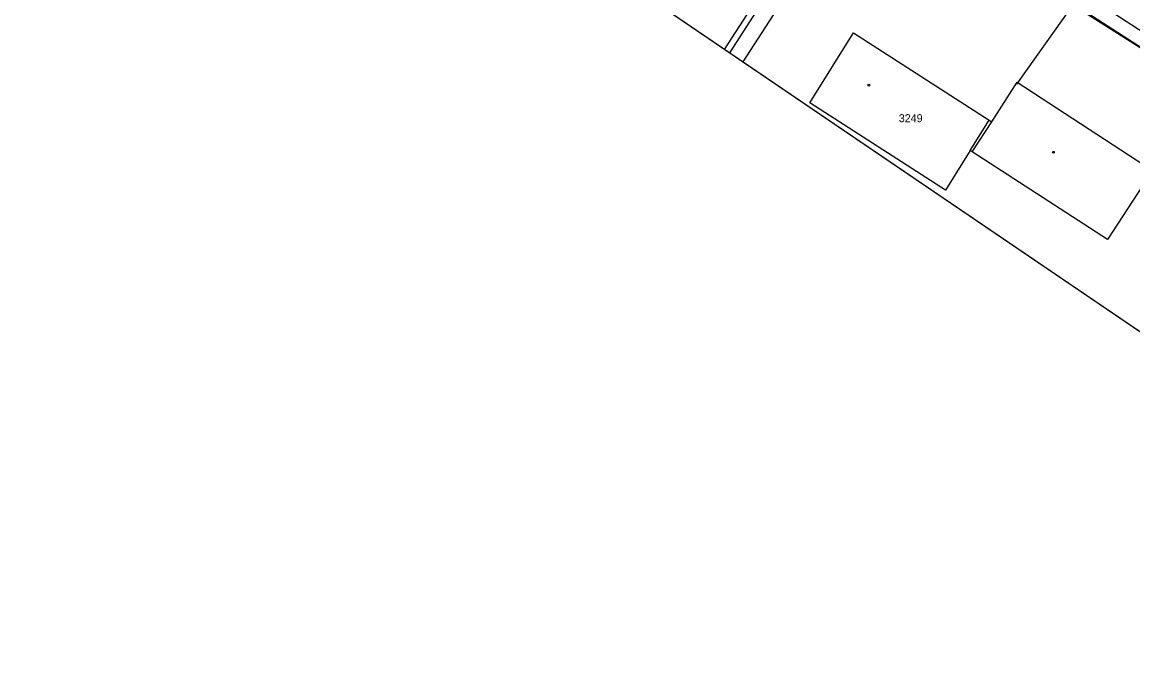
# Model space of a CAD drawing. Extents: x -621145 to -620023, y -1122866 to -1121971.
# Drawn here: x -620936.6 to -620728.5, y -1122562.6 to -1122442.6 of the extents above; entities that cross this region are included whole.
import ezdxf

# ---------------------------------------------------------------- set-up
doc = ezdxf.new("R2010")
doc.units = 0
for name, color, linetype in [('GasNet', 7, 'Continuous'), ('itself', 7, 'Continuous'), ('RÁMY', 7, 'Continuous'), ('VAS vodovod', 7, 'Continuous'), ('Vrstva 55', 7, 'Continuous'), ('Vrstva 56', 7, 'Continuous'), ('Vrstva 57', 7, 'Continuous')]:
    doc.layers.add(name, color=color, linetype=linetype)

msp = doc.modelspace()

# ---------------------------------------------------------------- linework, layer by layer
at = {"layer": 'GasNet'}
msp.add_lwpolyline([(-620780.25, -1122411.07), (-620780.49, -1122411.62), (-620780.55, -1122411.72), (-620781.12, -1122412.67), (-620781.53, -1122413.35), (-620786.71, -1122421.95), (-620795.26, -1122434.7), (-620804.04, -1122448.32)], dxfattribs=at)
at = {"layer": 'itself'}
msp.add_lwpolyline([(-620721.67, -1122450.84), (-620745.77, -1122435.49), (-620776.46, -1122415.3), (-620776.4, -1122414.33), (-620775.69, -1122413.16), (-620774.76, -1122411.29), (-620776.99, -1122409.87), (-620778.95, -1122408.64), (-620781.22, -1122407.1), (-620786.31, -1122404.21), (-620793, -1122399.61), (-620794.81, -1122398.03), (-620806.31, -1122390.88), (-620816.81, -1122384.12), (-620818.8, -1122383.36), (-620822.25, -1122382.5), (-620843.1, -1122368.97), (-620871.29, -1122351.22), (-620896.98, -1122334.7), (-620917.62, -1122321.73), (-620932.53, -1122311.53), (-620939.77, -1122306.09)], dxfattribs=at)
at = {"layer": 'RÁMY'}
for points in [[(-621061.56, -1122093.92), (-620106.07, -1122742.82), (-620189.51, -1122865.67), (-621144.99, -1122216.77)], [(-620887.83, -1122211.9), (-620106.07, -1122742.82), (-620189.51, -1122865.67), (-620971.26, -1122334.75)]]:
    msp.add_lwpolyline(points, close=True, dxfattribs=at)
at = {"layer": 'VAS vodovod'}
for points in [[(-620783.05, -1122410.36), (-620779.49, -1122412.44), (-620776.82, -1122413.57), (-620766.15, -1122419), (-620759.23, -1122423.16), (-620738.05, -1122436.88), (-620666.7, -1122483.31), (-620630.69, -1122506.76), (-620611.44, -1122519.95), (-620587.32, -1122536.52), (-620566.14, -1122551.51), (-620558.22, -1122559.71), (-620551.85, -1122569.08), (-620547.83, -1122576.32), (-620546.15, -1122586.98), (-620546.1, -1122587.26)], [(-620738.05, -1122436.88), (-620738.12, -1122437.06), (-620750.23, -1122454.2)]]:
    msp.add_lwpolyline(points, dxfattribs=at)
at = {"layer": 'Vrstva 55'}
for p, q in [((-620778.34, -1122414.11), (-620801.54, -1122450.02)), ((-620702.74, -1122462.95), (-620757.34, -1122427.68)), ((-620754.9, -1122461.23), (-620750.13, -1122453.84)), ((-620755.36, -1122460.94), (-620754.9, -1122461.23)), ((-620758.55, -1122466.88), (-620758.93, -1122466.63))]:
    msp.add_line(p, q, dxfattribs=at)
for points in [[(-620804.95, -1122447.7), (-620781.81, -1122411.87), (-620848.87, -1122368.55)], [(-620758.93, -1122466.63), (-620763.57, -1122474.01), (-620789, -1122457.71), (-620780.78, -1122444.6), (-620755.36, -1122460.94)], [(-620750.13, -1122453.84), (-620724.79, -1122470.34), (-620733.19, -1122483.27), (-620758.55, -1122466.88)]]:
    msp.add_lwpolyline(points, dxfattribs=at)
at = {"layer": 'Vrstva 56'}
for p, q in [((-620758.93, -1122466.63), (-620755.36, -1122460.94)), ((-620758.55, -1122466.88), (-620754.9, -1122461.23))]:
    msp.add_line(p, q, dxfattribs=at)
at = {"layer": 'Vrstva 57'}
for centre in [(-620777.9, -1122454.36), (-620743.34, -1122466.95)]:
    msp.add_circle(centre, 0.175, dxfattribs=at)

# ---------------------------------------------------------------- texts
msp.add_text('3249', height=1.5, dxfattribs=at).set_placement((-620772.31, -1122461.31))

doc.saveas('drawing.dxf')
